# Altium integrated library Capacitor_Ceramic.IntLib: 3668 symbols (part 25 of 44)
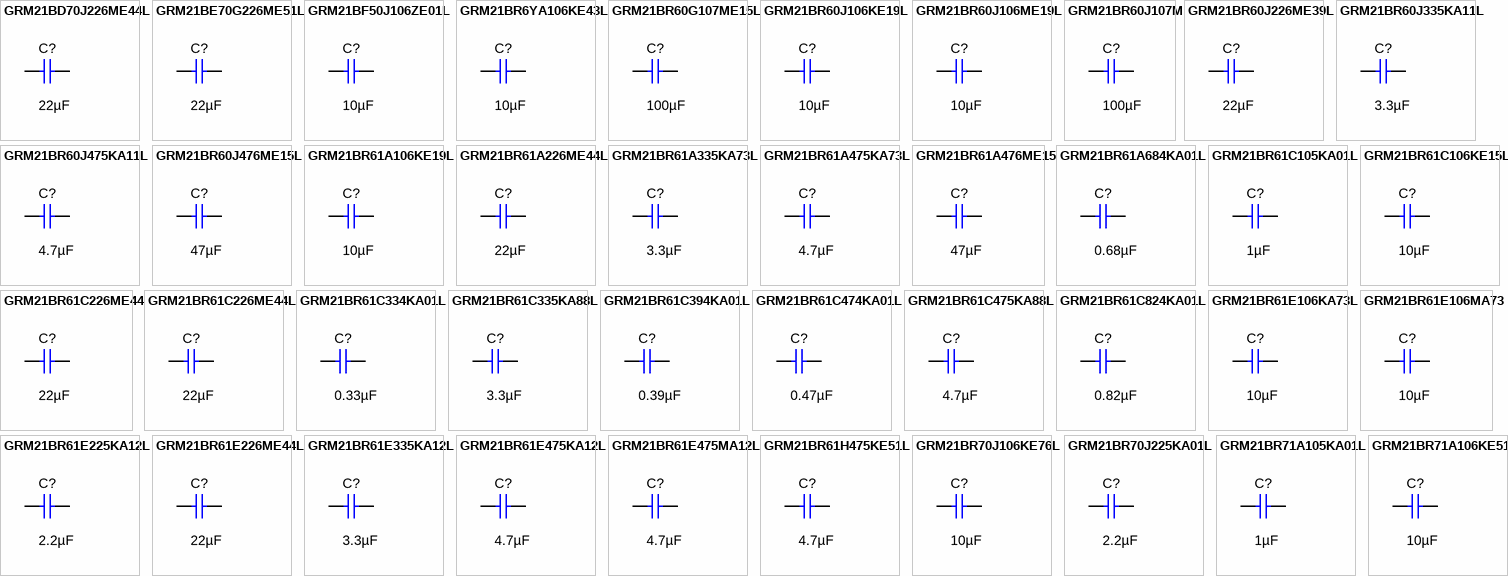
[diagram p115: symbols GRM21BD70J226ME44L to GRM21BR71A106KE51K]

## GRM21BR61C394KA01L
designator C?  ValueDisplayed: 0.39µF  (hidden comment: GRM21BR61C394KA01L)
CAP, CERM, 0.39 µF, 16 V,+/- 10%, X5R, 0805; Manufacturer: MuRata; Polarized: N; CompType: Capacitor; Value: 0.39uF; U/M: EA; Cap_F: 0.00000039; Tolerance_%: 10; VDC_V: 16; Value2: 16V; TaMin_C: -55; TaMax_C: 85; Cap_Case: 0805; SizeArea_mm2: 2.5; SizeAreaWB_mm2: 6.75; SizeX_mm: 2; SizeY_mm: 1.25; SizeZ_mm: 1.45; AEC Category: Q200
signal-integrity model Cap
simulation model Cap
footprint 0805_HV
footprint 0805_HV1
footprint 0805
footprint 0805M
footprint 0805L
pins: 1, 2

## GRM21BR61C474KA01L
designator C?  ValueDisplayed: 0.47µF  (hidden comment: GRM21BR61C474KA01L)
CAP, CERM, 0.47 µF, 16 V,+/- 10%, X5R, 0805; Manufacturer: MuRata; Polarized: N; CompType: Capacitor; Value: 0.47uF; U/M: EA; Cap_F: 0.00000047; Tolerance_%: 10; VDC_V: 16; Value2: 16V; TaMin_C: -55; TaMax_C: 85; Cap_Case: 0805; SizeArea_mm2: 2.5; SizeAreaWB_mm2: 6.75; SizeX_mm: 2; SizeY_mm: 1.25; SizeZ_mm: 1.45; AEC Category: Q200
signal-integrity model Cap
simulation model Cap
footprint 0805_HV
footprint 0805_HV1
footprint 0805
footprint 0805M
footprint 0805L
pins: 1, 2

## GRM21BR61C475KA88L
designator C?  ValueDisplayed: 4.7µF  (hidden comment: GRM21BR61C475KA88L)
CAP, CERM, 4.7 µF, 16 V,+/- 10%, X5R, 0805; Manufacturer: MuRata; Polarized: N; CompType: Capacitor; Value: 4.7uF; U/M: EA; Cap_F: 0.0000047; Tolerance_%: 10; ESR_ohm: 0.005; Value1: 0.005 ohm; VDC_V: 16; Value2: 16V; TaMin_C: -55; TaMax_C: 85; Cap_Case: 0805; SizeArea_mm2: 2.5; SizeAreaWB_mm2: 6.75; SizeX_mm: 2; SizeY_mm: 1.25; SizeZ_mm: 1.45; AEC Category: Q200; Green_Lifecycle: Active; Green_REACh: Passed
signal-integrity model Cap
simulation model Cap
footprint 0805_HV
footprint 0805_HV1
footprint 0805
footprint 0805M
footprint 0805L
pins: 1, 2

## GRM21BR61C824KA01L
designator C?  ValueDisplayed: 0.82µF  (hidden comment: GRM21BR61C824KA01L)
CAP, CERM, 0.82 µF, 16 V,+/- 10%, X5R, 0805; Manufacturer: MuRata; Polarized: N; CompType: Capacitor; Value: 0.82uF; U/M: EA; Cap_F: 0.00000082; Tolerance_%: 10; VDC_V: 16; Value2: 16V; TaMin_C: -55; TaMax_C: 85; Cap_Case: 0805; SizeArea_mm2: 2.5; SizeAreaWB_mm2: 6.75; SizeX_mm: 2; SizeY_mm: 1.25; SizeZ_mm: 1.45; AEC Category: Q200
signal-integrity model Cap
simulation model Cap
footprint 0805_HV
footprint 0805_HV1
footprint 0805
footprint 0805M
footprint 0805L
pins: 1, 2

## GRM21BR61E106KA73L
designator C?  ValueDisplayed: 10µF  (hidden comment: GRM21BR61E106KA73L)
CAP, CERM, 10 µF, 25 V,+/- 10%, X5R, 0805; Manufacturer: MuRata; Polarized: N; CompType: Capacitor; Value: 10uF; U/M: EA; Cap_F: 0.00001; Tolerance_%: 10; VDC_V: 25; Value2: 25V; TaMin_C: -55; TaMax_C: 85; Cap_Case: 0805; SizeArea_mm2: 2.5; SizeAreaWB_mm2: 6.75; SizeX_mm: 2; SizeY_mm: 1.25; SizeZ_mm: 1.45; AEC Category: Q200; Green_Lifecycle: Active; Green_REACh: Passed
signal-integrity model Cap
simulation model Cap
footprint 0805_HV
footprint 0805_HV1
footprint 0805
footprint 0805M
footprint 0805L
pins: 1, 2

## GRM21BR61E106MA73
designator C?  ValueDisplayed: 10µF  (hidden comment: GRM21BR61E106MA73)
CAP, CERM, 10 µF, 25 V,+/- 20%, X5R, 0805; Manufacturer: MuRata; Polarized: N; CompType: Capacitor; Value: 10uF; U/M: EA; Cap_F: 0.00001; Tolerance_%: 20; VDC_V: 25; Value2: 25V; TaMin_C: -55; TaMax_C: 85; Cap_Case: 0805; SizeArea_mm2: 2.5; SizeAreaWB_mm2: 6.75; SizeX_mm: 2; SizeY_mm: 1.25; SizeZ_mm: 1.45; AEC Category: Q200
signal-integrity model Cap
simulation model Cap
footprint 0805_HV
footprint 0805_HV1
footprint 0805
footprint 0805M
footprint 0805L
pins: 1, 2

## GRM21BR61E225KA12L
designator C?  ValueDisplayed: 2.2µF  (hidden comment: GRM21BR61E225KA12L)
CAP, CERM, 2.2 µF, 25 V,+/- 10%, X5R, 0805; Manufacturer: MuRata; Polarized: N; CompType: Capacitor; Value: 2.2uF; U/M: EA; Cap_F: 0.0000022; Tolerance_%: 10; ESR_ohm: 0.008; Value1: 0.008 ohm; VDC_V: 25; Value2: 25V; TaMin_C: -55; TaMax_C: 85; Cap_Case: 0805; SizeArea_mm2: 2.5; SizeAreaWB_mm2: 6.75; SizeX_mm: 2; SizeY_mm: 1.25; SizeZ_mm: 1.45; AEC Category: Q200; Green_Lifecycle: Active; Green_REACh: Passed
signal-integrity model Cap
simulation model Cap
footprint 0805_HV
footprint 0805_HV1
footprint 0805
footprint 0805M
footprint 0805L
pins: 1, 2

## GRM21BR61E226ME44L
designator C?  ValueDisplayed: 22µF  (hidden comment: GRM21BR61E226ME44L)
CAP, CERM, 22 µF, 25 V,+/- 20%, X5R, 0805; Manufacturer: MuRata; Polarized: N; CompType: Capacitor; Value: 22uF; U/M: EA; Cap_F: 0.000022; Tolerance_%: 20; VDC_V: 25; Value2: 25V; TaMin_C: -55; TaMax_C: 85; Cap_Case: 0805; SizeArea_mm2: 2.5; SizeAreaWB_mm2: 6.75; SizeX_mm: 2; SizeY_mm: 1.25; SizeZ_mm: 1.45; AEC Category: Q200; Green_Lifecycle: Active; Green_REACh: Passed
signal-integrity model Cap
simulation model Cap
footprint 0805_HV
footprint 0805_HV1
footprint 0805
footprint 0805M
footprint 0805L
pins: 1, 2

## GRM21BR61E335KA12L
designator C?  ValueDisplayed: 3.3µF  (hidden comment: GRM21BR61E335KA12L)
CAP, CERM, 3.3 µF, 25 V,+/- 10%, X5R, 0805; Manufacturer: MuRata; Polarized: N; CompType: Capacitor; Value: 3.3uF; U/M: EA; Cap_F: 0.0000033; Tolerance_%: 10; VDC_V: 25; Value2: 25V; TaMin_C: -55; TaMax_C: 85; Cap_Case: 0805; SizeArea_mm2: 2.5; SizeAreaWB_mm2: 6.75; SizeX_mm: 2; SizeY_mm: 1.25; SizeZ_mm: 1.45; AEC Category: Q200
signal-integrity model Cap
simulation model Cap
footprint 0805_HV
footprint 0805_HV1
footprint 0805
footprint 0805M
footprint 0805L
pins: 1, 2

## GRM21BR61E475KA12L
designator C?  ValueDisplayed: 4.7µF  (hidden comment: GRM21BR61E475KA12L)
CAP, CERM, 4.7 µF, 25 V,+/- 10%, X5R, 0805; Manufacturer: MuRata; Polarized: N; CompType: Capacitor; Value: 4.7uF; U/M: EA; Cap_F: 0.0000047; Tolerance_%: 10; ESR_ohm: 0.004; Value1: 0.004 ohm; VDC_V: 25; Value2: 25V; TaMin_C: -55; TaMax_C: 85; Cap_Case: 0805; SizeArea_mm2: 2.5; SizeAreaWB_mm2: 6.75; SizeX_mm: 2; SizeY_mm: 1.25; SizeZ_mm: 1.45; AEC Category: Q200; Green_Lifecycle: Active; Green_REACh: Passed
signal-integrity model Cap
simulation model Cap
footprint 0805_HV
footprint 0805_HV1
footprint 0805
footprint 0805M
footprint 0805L
pins: 1, 2

## GRM21BR61E475MA12L
designator C?  ValueDisplayed: 4.7µF  (hidden comment: GRM21BR61E475MA12L)
CAP, CERM, 4.7 µF, 25 V,+/- 20%, X5R, 0805; Manufacturer: MuRata; Polarized: N; CompType: Capacitor; Value: 4.7uF; U/M: EA; Cap_F: 0.0000047; Tolerance_%: 20; ESR_ohm: 0.002; Value1: 0.002 ohm; VDC_V: 25; Value2: 25V; IRMS_A: 7.29; TaMin_C: -55; TaMax_C: 125; Cap_Case: 0805; SizeArea_mm2: 2.5; SizeAreaWB_mm2: 6.75; SizeX_mm: 2; SizeY_mm: 1.25; SizeZ_mm: 1.45; AEC Category: Q200; Green_Lifecycle: Active; Green_REACh: Passed
signal-integrity model Cap
simulation model Cap
footprint 0805_HV
footprint 0805_HV1
footprint 0805
footprint 0805M
footprint 0805L
pins: 1, 2

## GRM21BR61H475KE51L
designator C?  ValueDisplayed: 4.7µF  (hidden comment: GRM21BR61H475KE51L)
CAP, CERM, 4.7 µF, 50 V,+/- 10%, X5R, 0805; Manufacturer: MuRata; Polarized: N; CompType: Capacitor; Value: 4.7uF; U/M: EA; Cap_F: 0.0000047; Tolerance_%: 10; VDC_V: 50; Value2: 50V; TaMin_C: -55; TaMax_C: 85; Cap_Case: 0805; SizeArea_mm2: 2.5; SizeAreaWB_mm2: 6.75; SizeX_mm: 2; SizeY_mm: 1.25; SizeZ_mm: 1.45; AEC Category: Q200
signal-integrity model Cap
simulation model Cap
footprint 0805_HV
footprint 0805_HV1
footprint 0805
footprint 0805M
footprint 0805L
pins: 1, 2

## GRM21BR70J106KE76L
designator C?  ValueDisplayed: 10µF  (hidden comment: GRM21BR70J106KE76L)
CAP, CERM, 10 µF, 6.3 V,+/- 10%, X7R, 0805; Manufacturer: MuRata; Polarized: N; CompType: Capacitor; Value: 10uF; U/M: EA; Cap_F: 0.00001; Tolerance_%: 10; VDC_V: 6.3; Value2: 6.3V; TaMin_C: -55; TaMax_C: 125; Cap_Case: 0805; SizeArea_mm2: 2.5; SizeAreaWB_mm2: 6.75; SizeX_mm: 2; SizeY_mm: 1.25; SizeZ_mm: 1.45; AEC Category: Q200; Green_Lifecycle: Active; Green_REACh: Passed
signal-integrity model Cap
simulation model Cap
footprint 0805_HV
footprint 0805_HV1
footprint 0805
footprint 0805M
footprint 0805L
pins: 1, 2

## GRM21BR70J225KA01L
designator C?  ValueDisplayed: 2.2µF  (hidden comment: GRM21BR70J225KA01L)
CAP, CERM, 2.2 µF, 6.3 V,+/- 10%, X7R, 0805; Manufacturer: MuRata; Polarized: N; CompType: Capacitor; Value: 2.2uF; U/M: EA; Cap_F: 0.0000022; Tolerance_%: 10; VDC_V: 6.3; Value2: 6.3V; TaMin_C: -55; TaMax_C: 125; Cap_Case: 0805; SizeArea_mm2: 2.5; SizeAreaWB_mm2: 6.75; SizeX_mm: 2; SizeY_mm: 1.25; SizeZ_mm: 1.45; AEC Category: Q200
signal-integrity model Cap
simulation model Cap
footprint 0805_HV
footprint 0805_HV1
footprint 0805
footprint 0805M
footprint 0805L
pins: 1, 2

## GRM21BR71A105KA01L
designator C?  ValueDisplayed: 1µF  (hidden comment: GRM21BR71A105KA01L)
CAP, CERM, 1 µF, 10 V,+/- 10%, X7R, 0805; Manufacturer: MuRata; Polarized: N; CompType: Capacitor; Value: 1uF; U/M: EA; Cap_F: 0.000001; Tolerance_%: 10; ESR_ohm: 0.007; Value1: 0.007 ohm; Value2: 10V; TaMin_C: -55; TaMax_C: 125; Cap_Case: 0805; SizeArea_mm2: 2.5; SizeAreaWB_mm2: 6.75; SizeX_mm: 2; SizeY_mm: 1.25; SizeZ_mm: 1.45; AEC Category: Q200
signal-integrity model Cap
simulation model Cap
footprint 0805_HV
footprint 0805_HV1
footprint 0805
footprint 0805M
footprint 0805L
pins: 1, 2

## GRM21BR71A106KE51K
designator C?  ValueDisplayed: 10µF  (hidden comment: GRM21BR71A106KE51K)
CAP, CERM, 10 µF, 10 V,+/- 10%, X7R, 0805; Manufacturer: MuRata; Polarized: N; CompType: Capacitor; Value: 10uF; U/M: EA; Cap_F: 0.00001; Tolerance_%: 10; Value2: 10V; TaMin_C: -55; TaMax_C: 125; Cap_Case: 0805; SizeArea_mm2: 2.5; SizeAreaWB_mm2: 6.75; SizeX_mm: 2; SizeY_mm: 1.25; SizeZ_mm: 1.45; AEC Category: Q200; Green_Lifecycle: Active; Green_REACh: Passed
signal-integrity model Cap
simulation model Cap
footprint 0805_HV
footprint 0805_HV1
footprint 0805
footprint 0805M
footprint 0805L
pins: 1, 2

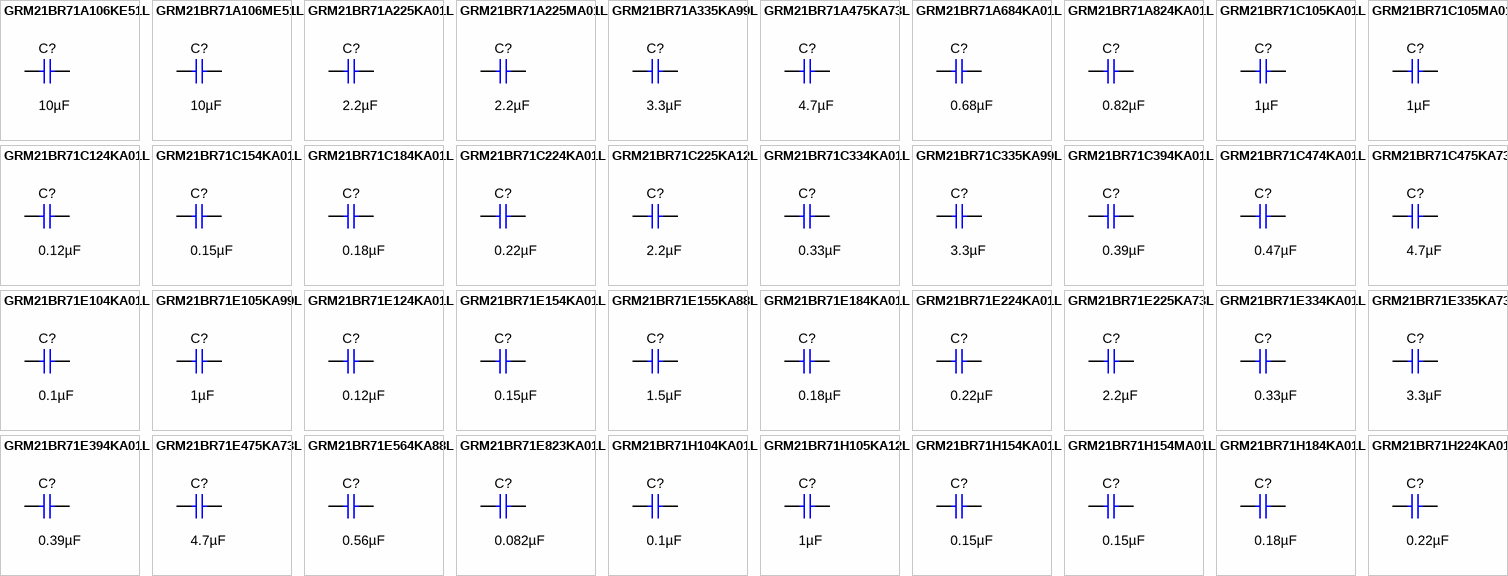
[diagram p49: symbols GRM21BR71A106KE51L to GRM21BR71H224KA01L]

## GRM21BR71A106KE51L
designator C?  ValueDisplayed: 10µF  (hidden comment: GRM21BR71A106KE51L)
CAP, CERM, 10 µF, 10 V,+/- 10%, X7R, 0805; Manufacturer: MuRata; Polarized: N; CompType: Capacitor; Value: 10uF; U/M: EA; Cap_F: 0.00001; Tolerance_%: 10; ESR_ohm: 0.003; Value1: 0.003 ohm; Value2: 10V; TaMin_C: -55; TaMax_C: 125; Cap_Case: 0805; SizeArea_mm2: 2.5; SizeAreaWB_mm2: 6.75; SizeX_mm: 2; SizeY_mm: 1.25; SizeZ_mm: 1.45; AEC Category: Q200; Green_Lifecycle: Active; Green_REACh: Passed
signal-integrity model Cap
simulation model Cap
footprint 0805_HV
footprint 0805_HV1
footprint 0805
footprint 0805M
footprint 0805L
pins: 1, 2

## GRM21BR71A106ME51L
designator C?  ValueDisplayed: 10µF  (hidden comment: GRM21BR71A106ME51L)
CAP, CERM, 10 µF, 10 V,+/- 20%, X7R, 0805; Manufacturer: MuRata; Polarized: N; CompType: Capacitor; Value: 10uF; U/M: EA; Cap_F: 0.00001; Tolerance_%: 20; VDC_V: 10; Value2: 10V; TaMin_C: -55; TaMax_C: 125; Cap_Case: 0805; SizeArea_mm2: 2.5; SizeAreaWB_mm2: 6.75; SizeX_mm: 2; SizeY_mm: 1.25; SizeZ_mm: 1.45; AEC Category: Q200; Green_Lifecycle: Active; Green_REACh: Passed
signal-integrity model Cap
simulation model Cap
footprint 0805_HV
footprint 0805_HV1
footprint 0805
footprint 0805M
footprint 0805L
pins: 1, 2

## GRM21BR71A225KA01L
designator C?  ValueDisplayed: 2.2µF  (hidden comment: GRM21BR71A225KA01L)
CAP, CERM, 2.2 µF, 10 V,+/- 10%, X7R, 0805; Manufacturer: MuRata; Polarized: N; CompType: Capacitor; Value: 2.2uF; U/M: EA; Cap_F: 0.0000022; Tolerance_%: 10; ESR_ohm: 0.006; Value1: 0.006 ohm; Value2: 10V; TaMin_C: -55; TaMax_C: 125; Cap_Case: 0805; SizeArea_mm2: 2.5; SizeAreaWB_mm2: 6.75; SizeX_mm: 2; SizeY_mm: 1.25; SizeZ_mm: 1.45; AEC Category: Q200; Green_Lifecycle: Active; Green_REACh: Passed
signal-integrity model Cap
simulation model Cap
footprint 0805_HV
footprint 0805_HV1
footprint 0805
footprint 0805M
footprint 0805L
pins: 1, 2

## GRM21BR71A225MA01L
designator C?  ValueDisplayed: 2.2µF  (hidden comment: GRM21BR71A225MA01L)
CAP, CERM, 2.2 µF, 10 V,+/- 20%, X7R, 0805; Manufacturer: MuRata; Polarized: N; CompType: Capacitor; Value: 2.2uF; U/M: EA; Cap_F: 0.0000022; Tolerance_%: 20; ESR_ohm: 0.006; Value1: 0.006 ohm; VDC_V: 10; Value2: 10V; TaMin_C: -55; TaMax_C: 125; Cap_Case: 0805; SizeArea_mm2: 2.5; SizeAreaWB_mm2: 6.75; SizeX_mm: 2; SizeY_mm: 1.25; SizeZ_mm: 1.45; AEC Category: Q200
signal-integrity model Cap
simulation model Cap
footprint 0805_HV
footprint 0805_HV1
footprint 0805
footprint 0805M
footprint 0805L
pins: 1, 2

## GRM21BR71A335KA99L
designator C?  ValueDisplayed: 3.3µF  (hidden comment: GRM21BR71A335KA99L)
CAP, CERM, 3.3 µF, 10 V,+/- 10%, X7R, 0805; Manufacturer: MuRata; Polarized: N; CompType: Capacitor; Value: 3.3uF; U/M: EA; Cap_F: 0.0000033; Tolerance_%: 10; Value2: 10V; TaMin_C: -55; TaMax_C: 125; Cap_Case: 0805; SizeArea_mm2: 2.5; SizeAreaWB_mm2: 6.75; SizeX_mm: 2; SizeY_mm: 1.25; SizeZ_mm: 1.45; AEC Category: Q200; Green_Lifecycle: Active; Green_REACh: Passed
signal-integrity model Cap
simulation model Cap
footprint 0805_HV
footprint 0805_HV1
footprint 0805
footprint 0805M
footprint 0805L
pins: 1, 2

## GRM21BR71A475KA73L
designator C?  ValueDisplayed: 4.7µF  (hidden comment: GRM21BR71A475KA73L)
CAP, CERM, 4.7 µF, 10 V,+/- 10%, X7R, 0805; Manufacturer: MuRata; Polarized: N; CompType: Capacitor; Value: 4.7uF; U/M: EA; Cap_F: 0.0000047; Tolerance_%: 10; Value2: 10V; TaMin_C: -55; TaMax_C: 125; Cap_Case: 0805; SizeArea_mm2: 2.5; SizeAreaWB_mm2: 6.75; SizeX_mm: 2; SizeY_mm: 1.25; SizeZ_mm: 1.45; AEC Category: Q200; Green_Lifecycle: Active; Green_REACh: Passed
signal-integrity model Cap
simulation model Cap
footprint 0805_HV
footprint 0805_HV1
footprint 0805
footprint 0805M
footprint 0805L
pins: 1, 2

## GRM21BR71A684KA01L
designator C?  ValueDisplayed: 0.68µF  (hidden comment: GRM21BR71A684KA01L)
CAP, CERM, 0.68 µF, 10 V,+/- 10%, X7R, 0805; Manufacturer: MuRata; Polarized: N; CompType: Capacitor; Value: 0.68uF; U/M: EA; Cap_F: 0.00000068; Tolerance_%: 10; Value2: 10V; TaMin_C: -55; TaMax_C: 125; Cap_Case: 0805; SizeArea_mm2: 2.5; SizeAreaWB_mm2: 6.75; SizeX_mm: 2; SizeY_mm: 1.25; SizeZ_mm: 1.45; AEC Category: Q200
signal-integrity model Cap
simulation model Cap
footprint 0805_HV
footprint 0805_HV1
footprint 0805
footprint 0805M
footprint 0805L
pins: 1, 2

## GRM21BR71A824KA01L
designator C?  ValueDisplayed: 0.82µF  (hidden comment: GRM21BR71A824KA01L)
CAP, CERM, 0.82 µF, 10 V,+/- 10%, X7R, 0805; Manufacturer: MuRata; Polarized: N; CompType: Capacitor; Value: 0.82uF; U/M: EA; Cap_F: 0.00000082; Tolerance_%: 10; Value2: 10V; TaMin_C: -55; TaMax_C: 125; Cap_Case: 0805; SizeArea_mm2: 2.5; SizeAreaWB_mm2: 6.75; SizeX_mm: 2; SizeY_mm: 1.25; SizeZ_mm: 1.45; AEC Category: Q200
signal-integrity model Cap
simulation model Cap
footprint 0805_HV
footprint 0805_HV1
footprint 0805
footprint 0805M
footprint 0805L
pins: 1, 2

## GRM21BR71C105KA01L
designator C?  ValueDisplayed: 1µF  (hidden comment: GRM21BR71C105KA01L)
CAP, CERM, 1 µF, 16 V,+/- 10%, X7R, 0805; Manufacturer: MuRata; Polarized: N; CompType: Capacitor; Value: 1uF; U/M: EA; Cap_F: 0.000001; Tolerance_%: 10; ESR_ohm: 0.003; Value1: 0.003 ohm; VDC_V: 16; Value2: 16V; TaMin_C: -55; TaMax_C: 125; Cap_Case: 0805; SizeArea_mm2: 2.5; SizeAreaWB_mm2: 6.75; SizeX_mm: 2; SizeY_mm: 1.25; SizeZ_mm: 1.45; AEC Category: Q200; Green_Lifecycle: Active; Green_REACh: Passed
signal-integrity model Cap
simulation model Cap
footprint 0805_HV
footprint 0805_HV1
footprint 0805
footprint 0805M
footprint 0805L
pins: 1, 2

## GRM21BR71C105MA01L
designator C?  ValueDisplayed: 1µF  (hidden comment: GRM21BR71C105MA01L)
CAP, CERM, 1 µF, 16 V,+/- 20%, X7R, 0805; Manufacturer: MuRata; Polarized: N; CompType: Capacitor; Value: 1uF; U/M: EA; Cap_F: 0.000001; Tolerance_%: 20; ESR_ohm: 0.003; Value1: 0.003 ohm; VDC_V: 16; Value2: 16V; TaMin_C: -55; TaMax_C: 125; Cap_Case: 0805; SizeArea_mm2: 2.5; SizeAreaWB_mm2: 6.75; SizeX_mm: 2; SizeY_mm: 1.25; SizeZ_mm: 1.45; AEC Category: Q200; Green_Lifecycle: Active; Green_REACh: Passed
signal-integrity model Cap
simulation model Cap
footprint 0805_HV
footprint 0805_HV1
footprint 0805
footprint 0805M
footprint 0805L
pins: 1, 2

## GRM21BR71C124KA01L
designator C?  ValueDisplayed: 0.12µF  (hidden comment: GRM21BR71C124KA01L)
CAP, CERM, 0.12 µF, 16 V,+/- 10%, X7R, 0805; Manufacturer: MuRata; Polarized: N; CompType: Capacitor; Value: 0.12uF; U/M: EA; Cap_F: 0.00000012; Tolerance_%: 10; VDC_V: 16; Value2: 16V; TaMin_C: -55; TaMax_C: 125; Cap_Case: 0805; SizeArea_mm2: 2.5; SizeAreaWB_mm2: 6.75; SizeX_mm: 2; SizeY_mm: 1.25; SizeZ_mm: 1.45; AEC Category: Q200
signal-integrity model Cap
simulation model Cap
footprint 0805_HV
footprint 0805_HV1
footprint 0805
footprint 0805M
footprint 0805L
pins: 1, 2

## GRM21BR71C154KA01L
designator C?  ValueDisplayed: 0.15µF  (hidden comment: GRM21BR71C154KA01L)
CAP, CERM, 0.15 µF, 16 V,+/- 10%, X7R, 0805; Manufacturer: MuRata; Polarized: N; CompType: Capacitor; Value: 0.15uF; U/M: EA; Cap_F: 0.00000015; Tolerance_%: 10; VDC_V: 16; Value2: 16V; TaMin_C: -55; TaMax_C: 125; Cap_Case: 0805; SizeArea_mm2: 2.5; SizeAreaWB_mm2: 6.75; SizeX_mm: 2; SizeY_mm: 1.25; SizeZ_mm: 1.45; AEC Category: Q200
signal-integrity model Cap
simulation model Cap
footprint 0805_HV
footprint 0805_HV1
footprint 0805
footprint 0805M
footprint 0805L
pins: 1, 2

## GRM21BR71C184KA01L
designator C?  ValueDisplayed: 0.18µF  (hidden comment: GRM21BR71C184KA01L)
CAP, CERM, 0.18 µF, 16 V,+/- 10%, X7R, 0805; Manufacturer: MuRata; Polarized: N; CompType: Capacitor; Value: 0.18uF; U/M: EA; Cap_F: 0.00000018; Tolerance_%: 10; VDC_V: 16; Value2: 16V; TaMin_C: -55; TaMax_C: 125; Cap_Case: 0805; SizeArea_mm2: 2.5; SizeAreaWB_mm2: 6.75; SizeX_mm: 2; SizeY_mm: 1.25; SizeZ_mm: 1.45; AEC Category: Q200
signal-integrity model Cap
simulation model Cap
footprint 0805_HV
footprint 0805_HV1
footprint 0805
footprint 0805M
footprint 0805L
pins: 1, 2

## GRM21BR71C224KA01L
designator C?  ValueDisplayed: 0.22µF  (hidden comment: GRM21BR71C224KA01L)
CAP, CERM, 0.22 µF, 16 V,+/- 10%, X7R, 0805; Manufacturer: MuRata; Polarized: N; CompType: Capacitor; Value: 0.22uF; U/M: EA; Cap_F: 0.00000022; Tolerance_%: 10; VDC_V: 16; Value2: 16V; TaMin_C: -55; TaMax_C: 125; Cap_Case: 0805; SizeArea_mm2: 2.5; SizeAreaWB_mm2: 6.75; SizeX_mm: 2; SizeY_mm: 1.25; SizeZ_mm: 1.45; AEC Category: Q200
signal-integrity model Cap
simulation model Cap
footprint 0805_HV
footprint 0805_HV1
footprint 0805
footprint 0805M
footprint 0805L
pins: 1, 2

## GRM21BR71C225KA12L
designator C?  ValueDisplayed: 2.2µF  (hidden comment: GRM21BR71C225KA12L)
CAP, CERM, 2.2 µF, 16 V,+/- 10%, X7R, 0805; Manufacturer: MuRata; Polarized: N; CompType: Capacitor; Value: 2.2uF; U/M: EA; Cap_F: 0.0000022; Tolerance_%: 10; ESR_ohm: 0.004; Value1: 0.004 ohm; VDC_V: 16; Value2: 16V; TaMin_C: -55; TaMax_C: 125; Cap_Case: 0805; SizeArea_mm2: 2.5; SizeAreaWB_mm2: 6.75; SizeX_mm: 2; SizeY_mm: 1.25; SizeZ_mm: 1.45; AEC Category: Q200; Green_Lifecycle: Active; Green_REACh: Passed
signal-integrity model Cap
simulation model Cap
footprint 0805_HV
footprint 0805_HV1
footprint 0805
footprint 0805M
footprint 0805L
pins: 1, 2

## GRM21BR71C334KA01L
designator C?  ValueDisplayed: 0.33µF  (hidden comment: GRM21BR71C334KA01L)
CAP, CERM, 0.33 µF, 16 V,+/- 10%, X7R, 0805; Manufacturer: MuRata; Polarized: N; CompType: Capacitor; Value: 0.33uF; U/M: EA; Cap_F: 0.00000033; Tolerance_%: 10; VDC_V: 16; Value2: 16V; TaMin_C: -55; TaMax_C: 125; Cap_Case: 0805; SizeArea_mm2: 2.5; SizeAreaWB_mm2: 6.75; SizeX_mm: 2; SizeY_mm: 1.25; SizeZ_mm: 1.45; AEC Category: Q200
signal-integrity model Cap
simulation model Cap
footprint 0805_HV
footprint 0805_HV1
footprint 0805
footprint 0805M
footprint 0805L
pins: 1, 2

## GRM21BR71C335KA99L
designator C?  ValueDisplayed: 3.3µF  (hidden comment: GRM21BR71C335KA99L)
CAP, CERM, 3.3 µF, 16 V,+/- 10%, X7R, 0805; Manufacturer: MuRata; Polarized: N; CompType: Capacitor; Value: 3.3uF; U/M: EA; Cap_F: 0.0000033; Tolerance_%: 10; VDC_V: 16; Value2: 16V; TaMin_C: -55; TaMax_C: 125; Cap_Case: 0805; SizeArea_mm2: 2.5; SizeAreaWB_mm2: 6.75; SizeX_mm: 2; SizeY_mm: 1.25; SizeZ_mm: 1.45; AEC Category: Q200
signal-integrity model Cap
simulation model Cap
footprint 0805_HV
footprint 0805_HV1
footprint 0805
footprint 0805M
footprint 0805L
pins: 1, 2

## GRM21BR71C394KA01L
designator C?  ValueDisplayed: 0.39µF  (hidden comment: GRM21BR71C394KA01L)
CAP, CERM, 0.39 µF, 16 V,+/- 10%, X7R, 0805; Manufacturer: MuRata; Polarized: N; CompType: Capacitor; Value: 0.39uF; U/M: EA; Cap_F: 0.00000039; Tolerance_%: 10; VDC_V: 16; Value2: 16V; TaMin_C: -55; TaMax_C: 125; Cap_Case: 0805; SizeArea_mm2: 2.5; SizeAreaWB_mm2: 6.75; SizeX_mm: 2; SizeY_mm: 1.25; SizeZ_mm: 1.45; AEC Category: Q200
signal-integrity model Cap
simulation model Cap
footprint 0805_HV
footprint 0805_HV1
footprint 0805
footprint 0805M
footprint 0805L
pins: 1, 2

## GRM21BR71C474KA01L
designator C?  ValueDisplayed: 0.47µF  (hidden comment: GRM21BR71C474KA01L)
CAP, CERM, 0.47 µF, 16 V,+/- 10%, X7R, 0805; Manufacturer: MuRata; Polarized: N; CompType: Capacitor; Value: 0.47uF; U/M: EA; Cap_F: 0.00000047; Tolerance_%: 10; VDC_V: 16; Value2: 16V; TaMin_C: -55; TaMax_C: 125; Cap_Case: 0805; SizeArea_mm2: 2.5; SizeAreaWB_mm2: 6.75; SizeX_mm: 2; SizeY_mm: 1.25; SizeZ_mm: 1.45; AEC Category: Q200; Green_Lifecycle: Active; Green_REACh: Passed
signal-integrity model Cap
simulation model Cap
footprint 0805_HV
footprint 0805_HV1
footprint 0805
footprint 0805M
footprint 0805L
pins: 1, 2

## GRM21BR71C475KA73L
designator C?  ValueDisplayed: 4.7µF  (hidden comment: GRM21BR71C475KA73L)
CAP, CERM, 4.7 µF, 16 V,+/- 10%, X7R, 0805; Manufacturer: MuRata; Polarized: N; CompType: Capacitor; Value: 4.7uF; U/M: EA; Cap_F: 0.0000047; Tolerance_%: 10; ESR_ohm: 0.006; Value1: 0.006 ohm; VDC_V: 16; Value2: 16V; TaMin_C: -55; TaMax_C: 125; Cap_Case: 0805; SizeArea_mm2: 2.5; SizeAreaWB_mm2: 6.75; SizeX_mm: 2; SizeY_mm: 1.25; SizeZ_mm: 1.45; AEC Category: Q200; Green_Lifecycle: Active; Green_REACh: Passed
signal-integrity model Cap
simulation model Cap
footprint 0805_HV
footprint 0805_HV1
footprint 0805
footprint 0805M
footprint 0805L
pins: 1, 2

## GRM21BR71E104KA01L
designator C?  ValueDisplayed: 0.1µF  (hidden comment: GRM21BR71E104KA01L)
CAP, CERM, 0.1 µF, 25 V,+/- 10%, X7R, 0805; Manufacturer: MuRata; Polarized: N; CompType: Capacitor; Value: 0.1uF; U/M: EA; Cap_F: 0.0000001; Tolerance_%: 10; VDC_V: 25; Value2: 25V; TaMin_C: -55; TaMax_C: 125; Cap_Case: 0805; SizeArea_mm2: 2.5; SizeAreaWB_mm2: 6.75; SizeX_mm: 2; SizeY_mm: 1.25; SizeZ_mm: 1.45; AEC Category: Q200; Green_Lifecycle: Active; Green_REACh: Passed
signal-integrity model Cap
simulation model Cap
footprint 0805_HV
footprint 0805_HV1
footprint 0805
footprint 0805M
footprint 0805L
pins: 1, 2

## GRM21BR71E105KA99L
designator C?  ValueDisplayed: 1µF  (hidden comment: GRM21BR71E105KA99L)
CAP, CERM, 1 µF, 25 V,+/- 10%, X7R, 0805; Manufacturer: MuRata; Polarized: N; CompType: Capacitor; Value: 1uF; U/M: EA; Cap_F: 0.000001; Tolerance_%: 10; VDC_V: 25; Value2: 25V; TaMin_C: -55; TaMax_C: 125; Cap_Case: 0805; SizeArea_mm2: 2.5; SizeAreaWB_mm2: 6.75; SizeX_mm: 2; SizeY_mm: 1.25; SizeZ_mm: 1.45; AEC Category: Q200; Green_Lifecycle: Active; Green_REACh: Passed
signal-integrity model Cap
simulation model Cap
footprint 0805_HV
footprint 0805_HV1
footprint 0805
footprint 0805M
footprint 0805L
pins: 1, 2

## GRM21BR71E124KA01L
designator C?  ValueDisplayed: 0.12µF  (hidden comment: GRM21BR71E124KA01L)
CAP, CERM, 0.12 µF, 25 V,+/- 10%, X7R, 0805; Manufacturer: MuRata; Polarized: N; CompType: Capacitor; Value: 0.12uF; U/M: EA; Cap_F: 0.00000012; Tolerance_%: 10; VDC_V: 25; Value2: 25V; TaMin_C: -55; TaMax_C: 125; Cap_Case: 0805; SizeArea_mm2: 2.5; SizeAreaWB_mm2: 6.75; SizeX_mm: 2; SizeY_mm: 1.25; SizeZ_mm: 1.45; AEC Category: Q200
signal-integrity model Cap
simulation model Cap
footprint 0805_HV
footprint 0805_HV1
footprint 0805
footprint 0805M
footprint 0805L
pins: 1, 2

## GRM21BR71E154KA01L
designator C?  ValueDisplayed: 0.15µF  (hidden comment: GRM21BR71E154KA01L)
CAP, CERM, 0.15 µF, 25 V,+/- 10%, X7R, 0805; Manufacturer: MuRata; Polarized: N; CompType: Capacitor; Value: 0.15uF; U/M: EA; Cap_F: 0.00000015; Tolerance_%: 10; VDC_V: 25; Value2: 25V; TaMin_C: -55; TaMax_C: 125; Cap_Case: 0805; SizeArea_mm2: 2.5; SizeAreaWB_mm2: 6.75; SizeX_mm: 2; SizeY_mm: 1.25; SizeZ_mm: 1.45; AEC Category: Q200
signal-integrity model Cap
simulation model Cap
footprint 0805_HV
footprint 0805_HV1
footprint 0805
footprint 0805M
footprint 0805L
pins: 1, 2

## GRM21BR71E155KA88L
designator C?  ValueDisplayed: 1.5µF  (hidden comment: GRM21BR71E155KA88L)
CAP, CERM, 1.5 µF, 25 V,+/- 10%, X7R, 0805; Manufacturer: MuRata; Polarized: N; CompType: Capacitor; Value: 1.5uF; U/M: EA; Cap_F: 0.0000015; Tolerance_%: 10; VDC_V: 25; Value2: 25V; TaMin_C: -55; TaMax_C: 125; Cap_Case: 0805; SizeArea_mm2: 2.5; SizeAreaWB_mm2: 6.75; SizeX_mm: 2; SizeY_mm: 1.25; SizeZ_mm: 1.45; AEC Category: Q200; Green_Lifecycle: Active; Green_REACh: Passed
signal-integrity model Cap
simulation model Cap
footprint 0805_HV
footprint 0805_HV1
footprint 0805
footprint 0805M
footprint 0805L
pins: 1, 2

## GRM21BR71E184KA01L
designator C?  ValueDisplayed: 0.18µF  (hidden comment: GRM21BR71E184KA01L)
CAP, CERM, 0.18 µF, 25 V,+/- 10%, X7R, 0805; Manufacturer: MuRata; Polarized: N; CompType: Capacitor; Value: 0.18uF; U/M: EA; Cap_F: 0.00000018; Tolerance_%: 10; VDC_V: 25; Value2: 25V; TaMin_C: -55; TaMax_C: 125; Cap_Case: 0805; SizeArea_mm2: 2.5; SizeAreaWB_mm2: 6.75; SizeX_mm: 2; SizeY_mm: 1.25; SizeZ_mm: 1.45; AEC Category: Q200
signal-integrity model Cap
simulation model Cap
footprint 0805_HV
footprint 0805_HV1
footprint 0805
footprint 0805M
footprint 0805L
pins: 1, 2

## GRM21BR71E224KA01L
designator C?  ValueDisplayed: 0.22µF  (hidden comment: GRM21BR71E224KA01L)
CAP, CERM, 0.22 µF, 25 V,+/- 10%, X7R, 0805; Manufacturer: MuRata; Polarized: N; CompType: Capacitor; Value: 0.22uF; U/M: EA; Cap_F: 0.00000022; Tolerance_%: 10; VDC_V: 25; Value2: 25V; TaMin_C: -55; TaMax_C: 125; Cap_Case: 0805; SizeArea_mm2: 2.5; SizeAreaWB_mm2: 6.75; SizeX_mm: 2; SizeY_mm: 1.25; SizeZ_mm: 1.45; AEC Category: Q200
signal-integrity model Cap
simulation model Cap
footprint 0805_HV
footprint 0805_HV1
footprint 0805
footprint 0805M
footprint 0805L
pins: 1, 2

## GRM21BR71E225KA73L
designator C?  ValueDisplayed: 2.2µF  (hidden comment: GRM21BR71E225KA73L)
CAP, CERM, 2.2 µF, 25 V,+/- 10%, X7R, 0805; Manufacturer: MuRata; Polarized: N; CompType: Capacitor; Value: 2.2uF; U/M: EA; Cap_F: 0.0000022; Tolerance_%: 10; ESR_ohm: 0.005; Value1: 0.005 ohm; VDC_V: 25; Value2: 25V; TaMin_C: -55; TaMax_C: 125; Cap_Case: 0805; SizeArea_mm2: 2.5; SizeAreaWB_mm2: 6.75; SizeX_mm: 2; SizeY_mm: 1.25; SizeZ_mm: 1.45; AEC Category: Q200; Green_Lifecycle: Active; Green_REACh: Passed
signal-integrity model Cap
simulation model Cap
footprint 0805_HV
footprint 0805_HV1
footprint 0805
footprint 0805M
footprint 0805L
pins: 1, 2

## GRM21BR71E334KA01L
designator C?  ValueDisplayed: 0.33µF  (hidden comment: GRM21BR71E334KA01L)
CAP, CERM, 0.33 µF, 25 V,+/- 10%, X7R, 0805; Manufacturer: MuRata; Polarized: N; CompType: Capacitor; Value: 0.33uF; U/M: EA; Cap_F: 0.00000033; Tolerance_%: 10; VDC_V: 25; Value2: 25V; TaMin_C: -55; TaMax_C: 125; Cap_Case: 0805; SizeArea_mm2: 2.5; SizeAreaWB_mm2: 6.75; SizeX_mm: 2; SizeY_mm: 1.25; SizeZ_mm: 1.45; AEC Category: Q200
signal-integrity model Cap
simulation model Cap
footprint 0805_HV
footprint 0805_HV1
footprint 0805
footprint 0805M
footprint 0805L
pins: 1, 2

## GRM21BR71E335KA73L
designator C?  ValueDisplayed: 3.3µF  (hidden comment: GRM21BR71E335KA73L)
CAP, CERM, 3.3 µF, 25 V,+/- 10%, X7R, 0805; Manufacturer: MuRata; Polarized: N; CompType: Capacitor; Value: 3.3uF; U/M: EA; Cap_F: 0.0000033; Tolerance_%: 10; VDC_V: 25; Value2: 25V; TaMin_C: -55; TaMax_C: 125; Cap_Case: 0805; SizeArea_mm2: 2.5; SizeAreaWB_mm2: 6.75; SizeX_mm: 2; SizeY_mm: 1.25; SizeZ_mm: 1.45; AEC Category: Q200
signal-integrity model Cap
simulation model Cap
footprint 0805_HV
footprint 0805_HV1
footprint 0805
footprint 0805M
footprint 0805L
pins: 1, 2

## GRM21BR71E394KA01L
designator C?  ValueDisplayed: 0.39µF  (hidden comment: GRM21BR71E394KA01L)
CAP, CERM, 0.39 µF, 25 V,+/- 10%, X7R, 0805; Manufacturer: MuRata; Polarized: N; CompType: Capacitor; Value: 0.39uF; U/M: EA; Cap_F: 0.00000039; Tolerance_%: 10; VDC_V: 25; Value2: 25V; TaMin_C: -55; TaMax_C: 125; Cap_Case: 0805; SizeArea_mm2: 2.5; SizeAreaWB_mm2: 6.75; SizeX_mm: 2; SizeY_mm: 1.25; SizeZ_mm: 1.45; AEC Category: Q200
signal-integrity model Cap
simulation model Cap
footprint 0805_HV
footprint 0805_HV1
footprint 0805
footprint 0805M
footprint 0805L
pins: 1, 2

## GRM21BR71E475KA73L
designator C?  ValueDisplayed: 4.7µF  (hidden comment: GRM21BR71E475KA73L)
CAP, CERM, 4.7 µF, 25 V,+/- 10%, X7R, 0805; Manufacturer: MuRata; Polarized: N; CompType: Capacitor; Value: 4.7uF; U/M: EA; Cap_F: 0.0000047; Tolerance_%: 10; VDC_V: 25; Value2: 25V; TaMin_C: -55; TaMax_C: 125; Cap_Case: 0805; SizeArea_mm2: 2.5; SizeAreaWB_mm2: 6.75; SizeX_mm: 2; SizeY_mm: 1.25; SizeZ_mm: 1.45; AEC Category: Q200
signal-integrity model Cap
simulation model Cap
footprint 0805_HV
footprint 0805_HV1
footprint 0805
footprint 0805M
footprint 0805L
pins: 1, 2

## GRM21BR71E564KA88L
designator C?  ValueDisplayed: 0.56µF  (hidden comment: GRM21BR71E564KA88L)
CAP, CERM, 0.56 µF, 25 V,+/- 10%, X7R, 0805; Manufacturer: MuRata; Polarized: N; CompType: Capacitor; Value: 0.56uF; U/M: EA; Cap_F: 0.00000056; Tolerance_%: 10; VDC_V: 25; Value2: 25V; TaMin_C: -55; TaMax_C: 125; Cap_Case: 0805; SizeArea_mm2: 2.5; SizeAreaWB_mm2: 6.75; SizeX_mm: 2; SizeY_mm: 1.25; SizeZ_mm: 1.45; AEC Category: Q200
signal-integrity model Cap
simulation model Cap
footprint 0805_HV
footprint 0805_HV1
footprint 0805
footprint 0805M
footprint 0805L
pins: 1, 2

## GRM21BR71E823KA01L
designator C?  ValueDisplayed: 0.082µF  (hidden comment: GRM21BR71E823KA01L)
CAP, CERM, 0.082 µF, 25 V,+/- 10%, X7R, 0805; Manufacturer: MuRata; Polarized: N; CompType: Capacitor; Value: 0.082uF; U/M: EA; Cap_F: 0.000000082; Tolerance_%: 10; VDC_V: 25; Value2: 25V; TaMin_C: -55; TaMax_C: 125; Cap_Case: 0805; SizeArea_mm2: 2.5; SizeAreaWB_mm2: 6.75; SizeX_mm: 2; SizeY_mm: 1.25; SizeZ_mm: 1.45; AEC Category: Q200
signal-integrity model Cap
simulation model Cap
footprint 0805_HV
footprint 0805_HV1
footprint 0805
footprint 0805M
footprint 0805L
pins: 1, 2

## GRM21BR71H104KA01L
designator C?  ValueDisplayed: 0.1µF  (hidden comment: GRM21BR71H104KA01L)
CAP, CERM, 0.1 µF, 50 V,+/- 10%, X7R, 0805; Manufacturer: MuRata; Polarized: N; CompType: Capacitor; Value: 0.1uF; U/M: EA; Cap_F: 0.0000001; Tolerance_%: 10; VDC_V: 50; Value2: 50V; TaMin_C: -55; TaMax_C: 125; Cap_Case: 0805; SizeArea_mm2: 2.5; SizeAreaWB_mm2: 6.75; SizeX_mm: 2; SizeY_mm: 1.25; SizeZ_mm: 1.45; AEC Category: Q200; Green_Lifecycle: Active; Green_REACh: Passed
signal-integrity model Cap
simulation model Cap
footprint 0805_HV
footprint 0805_HV1
footprint 0805
footprint 0805M
footprint 0805L
pins: 1, 2

## GRM21BR71H105KA12L
designator C?  ValueDisplayed: 1µF  (hidden comment: GRM21BR71H105KA12L)
CAP, CERM, 1 µF, 50 V,+/- 10%, X7R, 0805; Manufacturer: MuRata; Polarized: N; CompType: Capacitor; Value: 1uF; U/M: EA; Cap_F: 0.000001; Tolerance_%: 10; VDC_V: 50; Value2: 50V; TaMin_C: -55; TaMax_C: 125; Cap_Case: 0805; SizeArea_mm2: 2.5; SizeAreaWB_mm2: 6.75; SizeX_mm: 2; SizeY_mm: 1.25; SizeZ_mm: 1.45; AEC Category: Q200; Green_Lifecycle: Active; Green_REACh: Passed
signal-integrity model Cap
simulation model Cap
footprint 0805_HV
footprint 0805_HV1
footprint 0805
footprint 0805M
footprint 0805L
pins: 1, 2

## GRM21BR71H154KA01L
designator C?  ValueDisplayed: 0.15µF  (hidden comment: GRM21BR71H154KA01L)
CAP, CERM, 0.15 µF, 50 V,+/- 10%, X7R, 0805; Manufacturer: MuRata; Polarized: N; CompType: Capacitor; Value: 0.15uF; U/M: EA; Cap_F: 0.00000015; Tolerance_%: 10; VDC_V: 50; Value2: 50V; TaMin_C: -55; TaMax_C: 125; Cap_Case: 0805; SizeArea_mm2: 2.5; SizeAreaWB_mm2: 6.75; SizeX_mm: 2; SizeY_mm: 1.25; SizeZ_mm: 1.45; AEC Category: Q200
signal-integrity model Cap
simulation model Cap
footprint 0805_HV
footprint 0805_HV1
footprint 0805
footprint 0805M
footprint 0805L
pins: 1, 2

## GRM21BR71H154MA01L
designator C?  ValueDisplayed: 0.15µF  (hidden comment: GRM21BR71H154MA01L)
CAP, CERM, 0.15 µF, 50 V,+/- 20%, X7R, 0805; Manufacturer: MuRata; Polarized: N; CompType: Capacitor; Value: 0.15uF; U/M: EA; Cap_F: 0.00000015; Tolerance_%: 20; VDC_V: 50; Value2: 50V; TaMin_C: -55; TaMax_C: 125; Cap_Case: 0805; SizeArea_mm2: 2.5; SizeAreaWB_mm2: 6.75; SizeX_mm: 2; SizeY_mm: 1.25; SizeZ_mm: 1.45; AEC Category: Q200
signal-integrity model Cap
simulation model Cap
footprint 0805_HV
footprint 0805_HV1
footprint 0805
footprint 0805M
footprint 0805L
pins: 1, 2

## GRM21BR71H184KA01L
designator C?  ValueDisplayed: 0.18µF  (hidden comment: GRM21BR71H184KA01L)
CAP, CERM, 0.18 µF, 50 V,+/- 10%, X7R, 0805; Manufacturer: MuRata; Polarized: N; CompType: Capacitor; Value: 0.18uF; U/M: EA; Cap_F: 0.00000018; Tolerance_%: 10; VDC_V: 50; Value2: 50V; TaMin_C: -55; TaMax_C: 125; Cap_Case: 0805; SizeArea_mm2: 2.5; SizeAreaWB_mm2: 6.75; SizeX_mm: 2; SizeY_mm: 1.25; SizeZ_mm: 1.45; AEC Category: Q200
signal-integrity model Cap
simulation model Cap
footprint 0805_HV
footprint 0805_HV1
footprint 0805
footprint 0805M
footprint 0805L
pins: 1, 2

## GRM21BR71H224KA01L
designator C?  ValueDisplayed: 0.22µF  (hidden comment: GRM21BR71H224KA01L)
CAP, CERM, 0.22 µF, 50 V,+/- 10%, X7R, 0805; Manufacturer: MuRata; Polarized: N; CompType: Capacitor; Value: 0.22uF; U/M: EA; Cap_F: 0.00000022; Tolerance_%: 10; VDC_V: 50; Value2: 50V; TaMin_C: -55; TaMax_C: 125; Cap_Case: 0805; SizeArea_mm2: 2.5; SizeAreaWB_mm2: 6.75; SizeX_mm: 2; SizeY_mm: 1.25; SizeZ_mm: 1.45; AEC Category: Q200; Green_Lifecycle: Active; Green_REACh: Passed
signal-integrity model Cap
simulation model Cap
footprint 0805_HV
footprint 0805_HV1
footprint 0805
footprint 0805M
footprint 0805L
pins: 1, 2

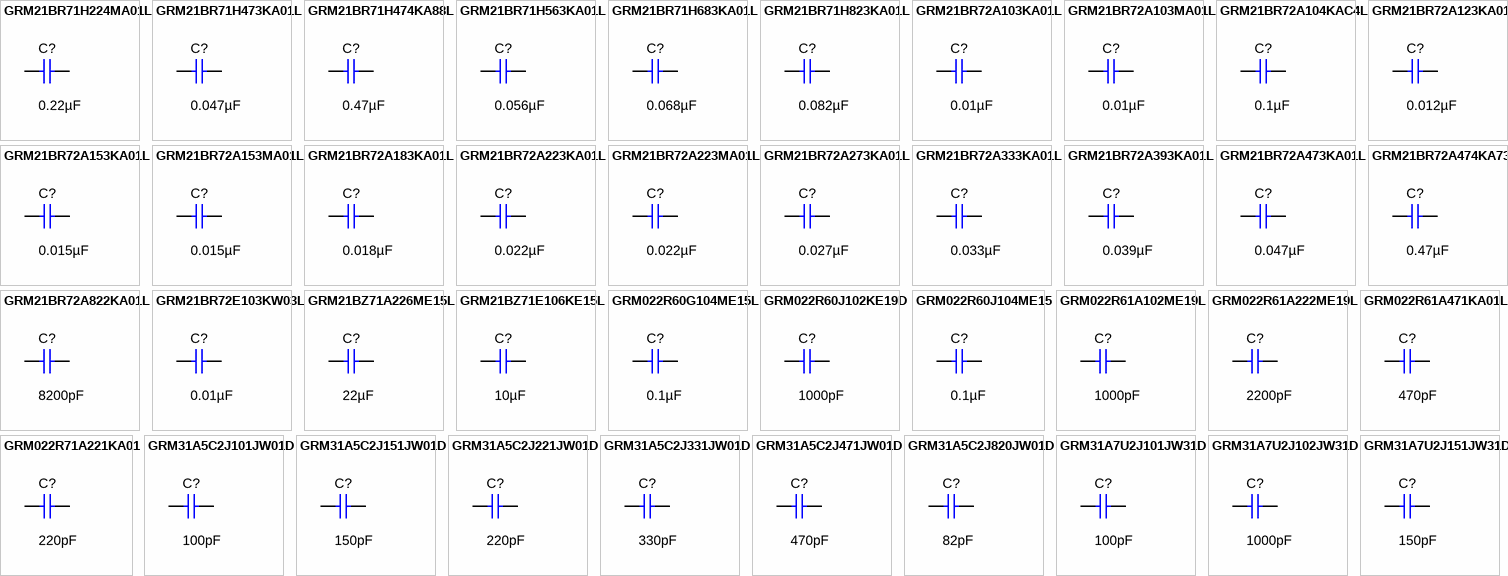
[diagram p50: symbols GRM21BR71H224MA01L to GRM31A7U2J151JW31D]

## GRM21BR71H224MA01L
designator C?  ValueDisplayed: 0.22µF  (hidden comment: GRM21BR71H224MA01L)
CAP, CERM, 0.22 µF, 50 V,+/- 20%, X7R, 0805; Manufacturer: MuRata; Polarized: N; CompType: Capacitor; Value: 0.22uF; U/M: EA; Cap_F: 0.00000022; Tolerance_%: 20; VDC_V: 50; Value2: 50V; TaMin_C: -55; TaMax_C: 125; Cap_Case: 0805; SizeArea_mm2: 2.5; SizeAreaWB_mm2: 6.75; SizeX_mm: 2; SizeY_mm: 1.25; SizeZ_mm: 1.45; AEC Category: Q200; Green_Lifecycle: Active; Green_REACh: Passed
signal-integrity model Cap
simulation model Cap
footprint 0805_HV
footprint 0805_HV1
footprint 0805
footprint 0805M
footprint 0805L
pins: 1, 2

## GRM21BR71H473KA01L
designator C?  ValueDisplayed: 0.047µF  (hidden comment: GRM21BR71H473KA01L)
CAP, CERM, 0.047 µF, 50 V,+/- 10%, X7R, 0805; Manufacturer: MuRata; Polarized: N; CompType: Capacitor; Value: 0.047uF; U/M: EA; Cap_F: 0.000000047; Tolerance_%: 10; VDC_V: 50; Value2: 50V; TaMin_C: -55; TaMax_C: 125; Cap_Case: 0805; SizeArea_mm2: 2.5; SizeAreaWB_mm2: 6.75; SizeX_mm: 2; SizeY_mm: 1.25; SizeZ_mm: 1.45; AEC Category: Q200; Green_Lifecycle: Active; Green_REACh: Passed
signal-integrity model Cap
simulation model Cap
footprint 0805_HV
footprint 0805_HV1
footprint 0805
footprint 0805M
footprint 0805L
pins: 1, 2

## GRM21BR71H474KA88L
designator C?  ValueDisplayed: 0.47µF  (hidden comment: GRM21BR71H474KA88L)
CAP, CERM, 0.47 µF, 50 V,+/- 10%, X7R, 0805; Manufacturer: MuRata; Polarized: N; CompType: Capacitor; Value: 0.47uF; U/M: EA; Cap_F: 0.00000047; Tolerance_%: 10; VDC_V: 50; Value2: 50V; TaMin_C: -55; TaMax_C: 125; Cap_Case: 0805; SizeArea_mm2: 2.5; SizeAreaWB_mm2: 6.75; SizeX_mm: 2; SizeY_mm: 1.25; SizeZ_mm: 1.45; AEC Category: Q200; Green_Lifecycle: Active; Green_REACh: Passed
signal-integrity model Cap
simulation model Cap
footprint 0805_HV
footprint 0805_HV1
footprint 0805
footprint 0805M
footprint 0805L
pins: 1, 2

## GRM21BR71H563KA01L
designator C?  ValueDisplayed: 0.056µF  (hidden comment: GRM21BR71H563KA01L)
CAP, CERM, 0.056 µF, 50 V,+/- 10%, X7R, 0805; Manufacturer: MuRata; Polarized: N; CompType: Capacitor; Value: 0.056uF; U/M: EA; Cap_F: 0.000000056; Tolerance_%: 10; VDC_V: 50; Value2: 50V; TaMin_C: -55; TaMax_C: 125; Cap_Case: 0805; SizeArea_mm2: 2.5; SizeAreaWB_mm2: 6.75; SizeX_mm: 2; SizeY_mm: 1.25; SizeZ_mm: 1.45; AEC Category: Q200
signal-integrity model Cap
simulation model Cap
footprint 0805_HV
footprint 0805_HV1
footprint 0805
footprint 0805M
footprint 0805L
pins: 1, 2

## GRM21BR71H683KA01L
designator C?  ValueDisplayed: 0.068µF  (hidden comment: GRM21BR71H683KA01L)
CAP, CERM, 0.068 µF, 50 V,+/- 10%, X7R, 0805; Manufacturer: MuRata; Polarized: N; CompType: Capacitor; Value: 0.068uF; U/M: EA; Cap_F: 0.000000068; Tolerance_%: 10; VDC_V: 50; Value2: 50V; TaMin_C: -55; TaMax_C: 125; Cap_Case: 0805; SizeArea_mm2: 2.5; SizeAreaWB_mm2: 6.75; SizeX_mm: 2; SizeY_mm: 1.25; SizeZ_mm: 1.45; AEC Category: Q200
signal-integrity model Cap
simulation model Cap
footprint 0805_HV
footprint 0805_HV1
footprint 0805
footprint 0805M
footprint 0805L
pins: 1, 2

## GRM21BR71H823KA01L
designator C?  ValueDisplayed: 0.082µF  (hidden comment: GRM21BR71H823KA01L)
CAP, CERM, 0.082 µF, 50 V,+/- 10%, X7R, 0805; Manufacturer: MuRata; Polarized: N; CompType: Capacitor; Value: 0.082uF; U/M: EA; Cap_F: 0.000000082; Tolerance_%: 10; VDC_V: 50; Value2: 50V; TaMin_C: -55; TaMax_C: 125; Cap_Case: 0805; SizeArea_mm2: 2.5; SizeAreaWB_mm2: 6.75; SizeX_mm: 2; SizeY_mm: 1.25; SizeZ_mm: 1.45; AEC Category: Q200
signal-integrity model Cap
simulation model Cap
footprint 0805_HV
footprint 0805_HV1
footprint 0805
footprint 0805M
footprint 0805L
pins: 1, 2

## GRM21BR72A103KA01L
designator C?  ValueDisplayed: 0.01µF  (hidden comment: GRM21BR72A103KA01L)
CAP, CERM, 0.01 µF, 100 V,+/- 10%, X7R, 0805; Manufacturer: MuRata; Polarized: N; CompType: Capacitor; Value: 0.01uF; U/M: EA; Cap_F: 0.00000001; Tolerance_%: 10; VDC_V: 100; Value2: 100V; TaMin_C: -55; TaMax_C: 125; Cap_Case: 0805; SizeArea_mm2: 2.5; SizeAreaWB_mm2: 6.75; SizeX_mm: 2; SizeY_mm: 1.25; SizeZ_mm: 1.45; AEC Category: Q200; Green_Lifecycle: Active; Green_REACh: Passed
signal-integrity model Cap
simulation model Cap
footprint 0805_HV
footprint 0805_HV1
footprint 0805
footprint 0805M
footprint 0805L
pins: 1, 2

## GRM21BR72A103MA01L
designator C?  ValueDisplayed: 0.01µF  (hidden comment: GRM21BR72A103MA01L)
CAP, CERM, 0.01 µF, 100 V,+/- 20%, X7R, 0805; Manufacturer: MuRata; Polarized: N; CompType: Capacitor; Value: 0.01uF; U/M: EA; Cap_F: 0.00000001; Tolerance_%: 20; VDC_V: 100; Value2: 100V; TaMin_C: -55; TaMax_C: 125; Cap_Case: 0805; SizeArea_mm2: 2.5; SizeAreaWB_mm2: 6.75; SizeX_mm: 2; SizeY_mm: 1.25; SizeZ_mm: 1.45; AEC Category: Q200
signal-integrity model Cap
simulation model Cap
footprint 0805_HV
footprint 0805_HV1
footprint 0805
footprint 0805M
footprint 0805L
pins: 1, 2

## GRM21BR72A104KAC4L
designator C?  ValueDisplayed: 0.1µF  (hidden comment: GRM21BR72A104KAC4L)
CAP, CERM, 0.1 µF, 100 V,+/- 10%, X7R, 0805; Manufacturer: MuRata; Polarized: N; CompType: Capacitor; Value: 0.1uF; U/M: EA; Cap_F: 0.0000001; Tolerance_%: 10; VDC_V: 100; Value2: 100V; TaMin_C: -55; TaMax_C: 125; Cap_Case: 0805; SizeArea_mm2: 2.5; SizeAreaWB_mm2: 6.75; SizeX_mm: 2; SizeY_mm: 1.25; SizeZ_mm: 1.45; AEC Category: Q200
signal-integrity model Cap
simulation model Cap
footprint 0805_HV
footprint 0805_HV1
footprint 0805
footprint 0805M
footprint 0805L
pins: 1, 2

## GRM21BR72A123KA01L
designator C?  ValueDisplayed: 0.012µF  (hidden comment: GRM21BR72A123KA01L)
CAP, CERM, 0.012 µF, 100 V,+/- 10%, X7R, 0805; Manufacturer: MuRata; Polarized: N; CompType: Capacitor; Value: 0.012uF; U/M: EA; Cap_F: 0.000000012; Tolerance_%: 10; VDC_V: 100; Value2: 100V; TaMin_C: -55; TaMax_C: 125; Cap_Case: 0805; SizeArea_mm2: 2.5; SizeAreaWB_mm2: 6.75; SizeX_mm: 2; SizeY_mm: 1.25; SizeZ_mm: 1.45; AEC Category: Q200
signal-integrity model Cap
simulation model Cap
footprint 0805_HV
footprint 0805_HV1
footprint 0805
footprint 0805M
footprint 0805L
pins: 1, 2

## GRM21BR72A153KA01L
designator C?  ValueDisplayed: 0.015µF  (hidden comment: GRM21BR72A153KA01L)
CAP, CERM, 0.015 µF, 100 V,+/- 10%, X7R, 0805; Manufacturer: MuRata; Polarized: N; CompType: Capacitor; Value: 0.015uF; U/M: EA; Cap_F: 0.000000015; Tolerance_%: 10; VDC_V: 100; Value2: 100V; TaMin_C: -55; TaMax_C: 125; Cap_Case: 0805; SizeArea_mm2: 2.5; SizeAreaWB_mm2: 6.75; SizeX_mm: 2; SizeY_mm: 1.25; SizeZ_mm: 1.45; AEC Category: Q200
signal-integrity model Cap
simulation model Cap
footprint 0805_HV
footprint 0805_HV1
footprint 0805
footprint 0805M
footprint 0805L
pins: 1, 2

## GRM21BR72A153MA01L
designator C?  ValueDisplayed: 0.015µF  (hidden comment: GRM21BR72A153MA01L)
CAP, CERM, 0.015 µF, 100 V,+/- 20%, X7R, 0805; Manufacturer: MuRata; Polarized: N; CompType: Capacitor; Value: 0.015uF; U/M: EA; Cap_F: 0.000000015; Tolerance_%: 20; VDC_V: 100; Value2: 100V; TaMin_C: -55; TaMax_C: 125; Cap_Case: 0805; SizeArea_mm2: 2.5; SizeAreaWB_mm2: 6.75; SizeX_mm: 2; SizeY_mm: 1.25; SizeZ_mm: 1.45; AEC Category: Q200
signal-integrity model Cap
simulation model Cap
footprint 0805_HV
footprint 0805_HV1
footprint 0805
footprint 0805M
footprint 0805L
pins: 1, 2

## GRM21BR72A183KA01L
designator C?  ValueDisplayed: 0.018µF  (hidden comment: GRM21BR72A183KA01L)
CAP, CERM, 0.018 µF, 100 V,+/- 10%, X7R, 0805; Manufacturer: MuRata; Polarized: N; CompType: Capacitor; Value: 0.018uF; U/M: EA; Cap_F: 0.000000018; Tolerance_%: 10; VDC_V: 100; Value2: 100V; TaMin_C: -55; TaMax_C: 125; Cap_Case: 0805; SizeArea_mm2: 2.5; SizeAreaWB_mm2: 6.75; SizeX_mm: 2; SizeY_mm: 1.25; SizeZ_mm: 1.45; AEC Category: Q200
signal-integrity model Cap
simulation model Cap
footprint 0805_HV
footprint 0805_HV1
footprint 0805
footprint 0805M
footprint 0805L
pins: 1, 2

## GRM21BR72A223KA01L
designator C?  ValueDisplayed: 0.022µF  (hidden comment: GRM21BR72A223KA01L)
CAP, CERM, 0.022 µF, 100 V,+/- 10%, X7R, 0805; Manufacturer: MuRata; Polarized: N; CompType: Capacitor; Value: 0.022uF; U/M: EA; Cap_F: 0.000000022; Tolerance_%: 10; VDC_V: 100; Value2: 100V; TaMin_C: -55; TaMax_C: 125; Cap_Case: 0805; SizeArea_mm2: 2.5; SizeAreaWB_mm2: 6.75; SizeX_mm: 2; SizeY_mm: 1.25; SizeZ_mm: 1.45; AEC Category: Q200
signal-integrity model Cap
simulation model Cap
footprint 0805_HV
footprint 0805_HV1
footprint 0805
footprint 0805M
footprint 0805L
pins: 1, 2

## GRM21BR72A223MA01L
designator C?  ValueDisplayed: 0.022µF  (hidden comment: GRM21BR72A223MA01L)
CAP, CERM, 0.022 µF, 100 V,+/- 20%, X7R, 0805; Manufacturer: MuRata; Polarized: N; CompType: Capacitor; Value: 0.022uF; U/M: EA; Cap_F: 0.000000022; Tolerance_%: 20; VDC_V: 100; Value2: 100V; TaMin_C: -55; TaMax_C: 125; Cap_Case: 0805; SizeArea_mm2: 2.5; SizeAreaWB_mm2: 6.75; SizeX_mm: 2; SizeY_mm: 1.25; SizeZ_mm: 1.45; AEC Category: Q200
signal-integrity model Cap
simulation model Cap
footprint 0805_HV
footprint 0805_HV1
footprint 0805
footprint 0805M
footprint 0805L
pins: 1, 2

## GRM21BR72A273KA01L
designator C?  ValueDisplayed: 0.027µF  (hidden comment: GRM21BR72A273KA01L)
CAP, CERM, 0.027 µF, 100 V,+/- 10%, X7R, 0805; Manufacturer: MuRata; Polarized: N; CompType: Capacitor; Value: 0.027uF; U/M: EA; Cap_F: 0.000000027; Tolerance_%: 10; VDC_V: 100; Value2: 100V; TaMin_C: -55; TaMax_C: 125; Cap_Case: 0805; SizeArea_mm2: 2.5; SizeAreaWB_mm2: 6.75; SizeX_mm: 2; SizeY_mm: 1.25; SizeZ_mm: 1.45; AEC Category: Q200
signal-integrity model Cap
simulation model Cap
footprint 0805_HV
footprint 0805_HV1
footprint 0805
footprint 0805M
footprint 0805L
pins: 1, 2

## GRM21BR72A333KA01L
designator C?  ValueDisplayed: 0.033µF  (hidden comment: GRM21BR72A333KA01L)
CAP, CERM, 0.033 µF, 100 V,+/- 10%, X7R, 0805; Manufacturer: MuRata; Polarized: N; CompType: Capacitor; Value: 0.033uF; U/M: EA; Cap_F: 0.000000033; Tolerance_%: 10; VDC_V: 100; Value2: 100V; TaMin_C: -55; TaMax_C: 125; Cap_Case: 0805; SizeArea_mm2: 2.5; SizeAreaWB_mm2: 6.75; SizeX_mm: 2; SizeY_mm: 1.25; SizeZ_mm: 1.45; AEC Category: Q200
signal-integrity model Cap
simulation model Cap
footprint 0805_HV
footprint 0805_HV1
footprint 0805
footprint 0805M
footprint 0805L
pins: 1, 2

## GRM21BR72A393KA01L
designator C?  ValueDisplayed: 0.039µF  (hidden comment: GRM21BR72A393KA01L)
CAP, CERM, 0.039 µF, 100 V,+/- 10%, X7R, 0805; Manufacturer: MuRata; Polarized: N; CompType: Capacitor; Value: 0.039uF; U/M: EA; Cap_F: 0.000000039; Tolerance_%: 10; VDC_V: 100; Value2: 100V; TaMin_C: -55; TaMax_C: 125; Cap_Case: 0805; SizeArea_mm2: 2.5; SizeAreaWB_mm2: 6.75; SizeX_mm: 2; SizeY_mm: 1.25; SizeZ_mm: 1.45; AEC Category: Q200
signal-integrity model Cap
simulation model Cap
footprint 0805_HV
footprint 0805_HV1
footprint 0805
footprint 0805M
footprint 0805L
pins: 1, 2

## GRM21BR72A473KA01L
designator C?  ValueDisplayed: 0.047µF  (hidden comment: GRM21BR72A473KA01L)
CAP, CERM, 0.047 µF, 100 V,+/- 10%, X7R, 0805; Manufacturer: MuRata; Polarized: N; CompType: Capacitor; Value: 0.047uF; U/M: EA; Cap_F: 0.000000047; Tolerance_%: 10; VDC_V: 100; Value2: 100V; TaMin_C: -55; TaMax_C: 125; Cap_Case: 0805; SizeArea_mm2: 2.5; SizeAreaWB_mm2: 6.75; SizeX_mm: 2; SizeY_mm: 1.25; SizeZ_mm: 1.45; AEC Category: Q200
signal-integrity model Cap
simulation model Cap
footprint 0805_HV
footprint 0805_HV1
footprint 0805
footprint 0805M
footprint 0805L
pins: 1, 2

## GRM21BR72A474KA73L
designator C?  ValueDisplayed: 0.47µF  (hidden comment: GRM21BR72A474KA73L)
CAP, CERM, 0.47 µF, 100 V,+/- 10%, X7R, 0805; Manufacturer: MuRata; Polarized: N; CompType: Capacitor; Value: 0.47uF; U/M: EA; Cap_F: 0.00000047; Tolerance_%: 10; VDC_V: 100; Value2: 100V; TaMin_C: -55; TaMax_C: 125; Cap_Case: 0805; SizeArea_mm2: 2.5; SizeAreaWB_mm2: 6.75; SizeX_mm: 2; SizeY_mm: 1.25; SizeZ_mm: 1.45; AEC Category: Q200; Green_Lifecycle: Active; Green_REACh: Passed
signal-integrity model Cap
simulation model Cap
footprint 0805_HV
footprint 0805_HV1
footprint 0805
footprint 0805M
footprint 0805L
pins: 1, 2

## GRM21BR72A822KA01L
designator C?  ValueDisplayed: 8200pF  (hidden comment: GRM21BR72A822KA01L)
CAP, CERM, 8200 pF, 100 V,+/- 10%, X7R, 0805; Manufacturer: MuRata; Polarized: N; CompType: Capacitor; Value: 8200pF; U/M: EA; Cap_F: 0.0000000082; Tolerance_%: 10; VDC_V: 100; Value2: 100V; TaMin_C: -55; TaMax_C: 125; Cap_Case: 0805; SizeArea_mm2: 2.5; SizeAreaWB_mm2: 6.75; SizeX_mm: 2; SizeY_mm: 1.25; SizeZ_mm: 1.45; AEC Category: Q200
signal-integrity model Cap
simulation model Cap
footprint 0805_HV
footprint 0805_HV1
footprint 0805
footprint 0805M
footprint 0805L
pins: 1, 2

## GRM21BR72E103KW03L
designator C?  ValueDisplayed: 0.01µF  (hidden comment: GRM21BR72E103KW03L)
CAP, CERM, 0.01 µF, 250 V,+/- 10%, X7R, 0805; Manufacturer: MuRata; Polarized: N; CompType: Capacitor; Value: 0.01uF; U/M: EA; Cap_F: 0.00000001; Tolerance_%: 10; VDC_V: 250; Value2: 250V; TaMin_C: -55; TaMax_C: 125; Cap_Case: 0805; SizeArea_mm2: 2.5; SizeAreaWB_mm2: 6.75; SizeX_mm: 2; SizeY_mm: 1.25; SizeZ_mm: 1.45; AEC Category: Q200; Green_Lifecycle: Not Set; Green_REACh: Incomplete
signal-integrity model Cap
simulation model Cap
footprint 0805_HV
footprint 0805_HV1
footprint 0805
footprint 0805M
footprint 0805L
pins: 1, 2

## GRM21BZ71A226ME15L
designator C?  ValueDisplayed: 22µF  (hidden comment: GRM21BZ71A226ME15L)
CAP, CERM, 22 µF, 10 V,+/- 20%, X7R, 0805; Manufacturer: MuRata; Polarized: N; CompType: Capacitor; Value: 22uF; U/M: EA; Cap_F: 0.000022; Tolerance_%: 20; VDC_V: 10; Value2: 10V; TaMin_C: -55; TaMax_C: 125; Cap_Case: 0805; SizeArea_mm2: 2.5; SizeAreaWB_mm2: 6.75; SizeX_mm: 2; SizeY_mm: 1.25; SizeZ_mm: 1.45; AEC Category: Q200
signal-integrity model Cap
simulation model Cap
footprint 0805_HV
footprint 0805_HV1
footprint 0805
footprint 0805M
footprint 0805L
pins: 1, 2

## GRM21BZ71E106KE15L
designator C?  ValueDisplayed: 10µF  (hidden comment: GRM21BZ71E106KE15L)
CAP, CERM, 10 µF, 25 V,+/- 10%, X7R, 0805; Manufacturer: MuRata; Polarized: N; CompType: Capacitor; Value: 10uF; U/M: EA; Cap_F: 0.00001; Tolerance_%: 10; VDC_V: 25; Value2: 25V; TaMin_C: -55; TaMax_C: 125; Cap_Case: 0805; SizeArea_mm2: 2.5; SizeAreaWB_mm2: 6.75; SizeX_mm: 2; SizeY_mm: 1.25; SizeZ_mm: 1.45; AEC Category: Q200
signal-integrity model Cap
simulation model Cap
footprint 0805_HV
footprint 0805_HV1
footprint 0805
footprint 0805M
footprint 0805L
pins: 1, 2

## GRM022R60G104ME15L
designator C?  ValueDisplayed: 0.1µF  (hidden comment: GRM022R60G104ME15L)
CAP, CERM, 0.1 µF, 4 V,+/- 20%, X5R, 01005; Manufacturer: MuRata; Polarized: N; CompType: Capacitor; Value: 0.1uF; U/M: EA; Cap_F: 0.0000001; Tolerance_%: 20; VDC_V: 4; Value2: 4V; TaMin_C: -55; TaMax_C: 85; Cap_Case: 01005; SizeArea_mm2: 0.08; SizeAreaWB_mm2: 1.68; SizeX_mm: 0.4; SizeY_mm: 0.2; AEC Category: Q200
signal-integrity model Cap
simulation model Cap
footprint 01005
pins: 1, 2

## GRM022R60J102KE19D
designator C?  ValueDisplayed: 1000pF  (hidden comment: GRM022R60J102KE19D)
CAP, CERM, 1000 pF, 6.3 V,+/- 10%, X5R, 01005; Manufacturer: MuRata; Polarized: N; CompType: Capacitor; Value: 1000pF; U/M: EA; Cap_F: 0.000000001; Tolerance_%: 10; VDC_V: 6.3; Value2: 6.3V; TaMin_C: -55; TaMax_C: 85; Cap_Case: 01005; SizeArea_mm2: 0.08; SizeAreaWB_mm2: 1.68; SizeX_mm: 0.4; SizeY_mm: 0.2; AEC Category: Q200
signal-integrity model Cap
simulation model Cap
footprint 01005
pins: 1, 2

## GRM022R60J104ME15
designator C?  ValueDisplayed: 0.1µF  (hidden comment: GRM022R60J104ME15)
CAP, CERM, 0.1 µF, 6.3 V,+/- 20%, X5R, 01005; Manufacturer: MuRata; Polarized: N; CompType: Capacitor; Value: 0.1uF; U/M: EA; Cap_F: 0.0000001; Tolerance_%: 20; VDC_V: 6.3; Value2: 6.3V; TaMin_C: -55; TaMax_C: 85; Cap_Case: 01005; SizeArea_mm2: 0.08; SizeAreaWB_mm2: 1.68; SizeX_mm: 0.4; SizeY_mm: 0.2; AEC Category: Q200
signal-integrity model Cap
simulation model Cap
footprint 01005
pins: 1, 2

## GRM022R61A102ME19L
designator C?  ValueDisplayed: 1000pF  (hidden comment: GRM022R61A102ME19L)
CAP, CERM, 1000 pF, 10 V,+/- 20%, X5R, 01005; Manufacturer: MuRata; Polarized: N; CompType: Capacitor; Value: 1000pF; U/M: EA; Cap_F: 0.000000001; Tolerance_%: 20; VDC_V: 10; Value2: 10V; TaMin_C: -55; TaMax_C: 85; Cap_Case: 01005; SizeArea_mm2: 0.08; SizeAreaWB_mm2: 1.68; SizeX_mm: 0.4; SizeY_mm: 0.2; AEC Category: Q200
signal-integrity model Cap
simulation model Cap
footprint 01005
pins: 1, 2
